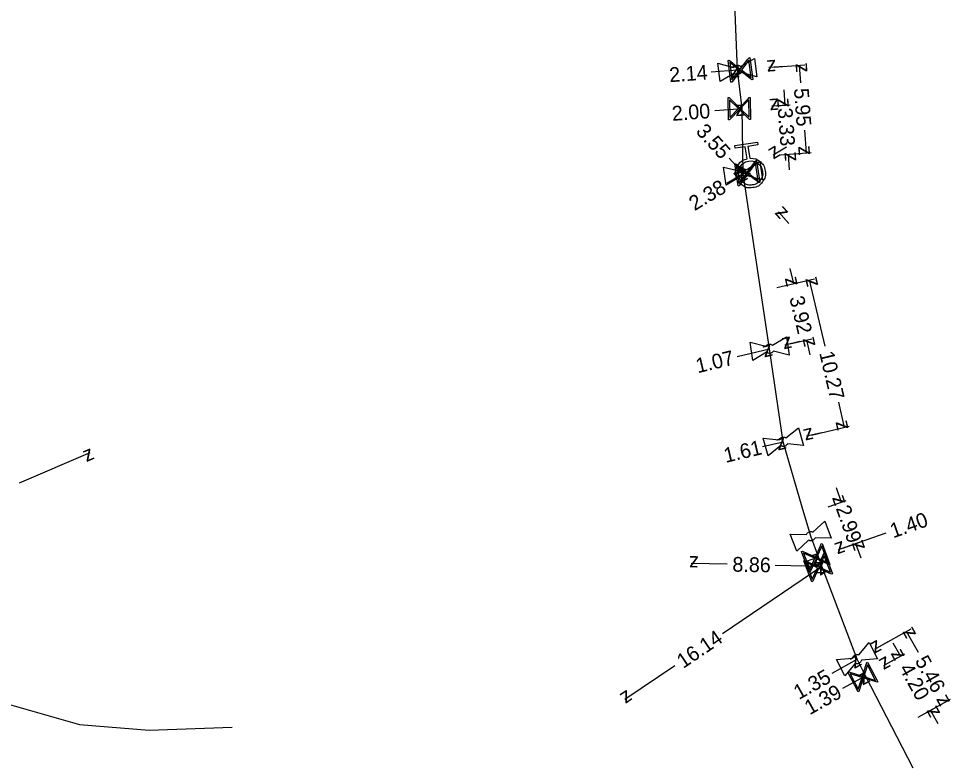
# Model space of a CAD drawing. Extents: x -638315 to -636370, y -1116147 to -1115110.
# Drawn here: x -637168.7 to -637105.5, y -1115879.5 to -1115828.9 of the extents above; entities that cross this region are included whole.
import ezdxf

# ---------------------------------------------------------------- set-up
doc = ezdxf.new("R2010")
doc.units = 0
for name, color, linetype in [('Default', 7, 'Continuous'), ('VP Hydrant', 7, 'Continuous'), ('VP Kótování', 7, 'Continuous'), ('VP Lomový bod', 7, 'Continuous'), ('VP Přípojka', 7, 'Continuous'), ('VP Řad', 7, 'Continuous'), ('VP Šoupě', 7, 'Continuous')]:
    doc.layers.add(name, color=color, linetype=linetype)

msp = doc.modelspace()

# ---------------------------------------------------------------- linework, layer by layer
at = {"layer": 'Default'}
for points in [[(-637120.251, -1115832.204), (-637120.222, -1115832.16), (-637120.178, -1115832.127), (-637120.111, -1115832.077), (-637120.03, -1115832.067), (-637119.948, -1115832.057), (-637119.868, -1115832.089), (-637119.819, -1115832.109), (-637119.78, -1115832.145)], [(-637119.729, -1115832.55), (-637119.758, -1115832.594), (-637119.8, -1115832.626), (-637119.87, -1115832.677), (-637119.951, -1115832.687), (-637120.032, -1115832.697), (-637120.11, -1115832.665), (-637120.161, -1115832.644), (-637120.2, -1115832.609)], [(-637119.158, -1115838.372), (-637118.798, -1115838.347), (-637118.505, -1115838.565), (-637118.173, -1115838.811), (-637118.111, -1115839.222), (-637118.049, -1115839.632), (-637118.295, -1115839.964), (-637118.541, -1115840.297), (-637118.952, -1115840.359), (-637119.359, -1115840.421), (-637119.693, -1115840.176), (-637120.026, -1115839.931), (-637120.088, -1115839.522), (-637120.15, -1115839.11), (-637119.907, -1115838.777), (-637119.691, -1115838.48), (-637119.34, -1115838.399)], [(-637119.224, -1115838.565), (-637119.558, -1115838.616), (-637119.757, -1115838.886), (-637119.956, -1115839.156), (-637119.905, -1115839.49), (-637119.855, -1115839.824), (-637119.585, -1115840.023), (-637119.314, -1115840.222), (-637118.98, -1115840.172), (-637118.648, -1115840.122), (-637118.448, -1115839.851), (-637118.248, -1115839.581), (-637118.299, -1115839.247), (-637118.349, -1115838.913), (-637118.619, -1115838.714), (-637118.89, -1115838.515), (-637119.224, -1115838.565)], [(-637119.875, -1115839.226), (-637119.847, -1115839.181), (-637119.804, -1115839.147), (-637119.738, -1115839.095), (-637119.657, -1115839.083), (-637119.576, -1115839.071), (-637119.495, -1115839.101), (-637119.445, -1115839.12), (-637119.405, -1115839.155)], [(-637119.344, -1115839.559), (-637119.372, -1115839.603), (-637119.414, -1115839.636), (-637119.482, -1115839.689), (-637119.563, -1115839.701), (-637119.644, -1115839.713), (-637119.723, -1115839.683), (-637119.774, -1115839.664), (-637119.814, -1115839.629)], [(-637118.074, -1115851.113), (-637118.046, -1115851.068), (-637118.003, -1115851.035), (-637117.937, -1115850.983), (-637117.856, -1115850.971), (-637117.775, -1115850.959), (-637117.694, -1115850.991), (-637117.644, -1115851.009), (-637117.604, -1115851.044)], [(-637117.545, -1115851.449), (-637117.573, -1115851.492), (-637117.615, -1115851.526), (-637117.684, -1115851.578), (-637117.765, -1115851.59), (-637117.845, -1115851.601), (-637117.924, -1115851.571), (-637117.975, -1115851.551), (-637118.015, -1115851.517)], [(-637117.164, -1115857.461), (-637117.143, -1115857.413), (-637117.104, -1115857.374), (-637117.046, -1115857.313), (-637116.967, -1115857.29), (-637116.888, -1115857.268), (-637116.804, -1115857.287), (-637116.752, -1115857.299), (-637116.708, -1115857.328)], [(-637116.594, -1115857.721), (-637116.616, -1115857.768), (-637116.653, -1115857.807), (-637116.714, -1115857.868), (-637116.793, -1115857.891), (-637116.871, -1115857.913), (-637116.953, -1115857.894), (-637117.006, -1115857.881), (-637117.05, -1115857.852)], [(-637115.313, -1115863.883), (-637115.295, -1115863.833), (-637115.26, -1115863.791), (-637115.206, -1115863.727), (-637115.13, -1115863.698), (-637115.053, -1115863.669), (-637114.967, -1115863.682), (-637114.915, -1115863.69), (-637114.869, -1115863.716)], [(-637114.725, -1115864.098), (-637114.743, -1115864.147), (-637114.777, -1115864.189), (-637114.833, -1115864.254), (-637114.91, -1115864.283), (-637114.986, -1115864.312), (-637115.069, -1115864.299), (-637115.123, -1115864.29), (-637115.17, -1115864.265)], [(-637112.184, -1115872.257), (-637112.172, -1115872.206), (-637112.142, -1115872.16), (-637112.095, -1115872.09), (-637112.023, -1115872.052), (-637111.95, -1115872.015), (-637111.863, -1115872.018), (-637111.81, -1115872.02), (-637111.761, -1115872.04)], [(-637111.574, -1115872.404), (-637111.587, -1115872.454), (-637111.616, -1115872.499), (-637111.664, -1115872.571), (-637111.737, -1115872.608), (-637111.81, -1115872.645), (-637111.894, -1115872.642), (-637111.948, -1115872.64), (-637111.997, -1115872.62)]]:
    msp.add_open_spline(points, degree=3, dxfattribs=at)
at = {"layer": 'VP Hydrant'}
msp.add_lwpolyline([(-637119.34, -1115838.399), (-637119.462, -1115837.588), (-637120.144, -1115837.691), (-637120.172, -1115837.51), (-637118.627, -1115837.276), (-637118.599, -1115837.457), (-637119.281, -1115837.56), (-637119.158, -1115838.372)], dxfattribs=at)
at = {"layer": 'VP Kótování'}
for points in [[(-637116.808, -1115832.144), (-637117.855, -1115832.221)], [(-637117.506, -1115832.195), (-637115.425, -1115832.043)], [(-637115.686, -1115833.258), (-637115.774, -1115832.069)], [(-637121.766, -1115832.507), (-637119.99, -1115832.377)], [(-637116.849, -1115833.728), (-637116.772, -1115834.775)], [(-637121.531, -1115835.123), (-637119.661, -1115834.986)], [(-637116.616, -1115834.763), (-637117.663, -1115834.84)], [(-637117.314, -1115834.814), (-637116.423, -1115834.749)], [(-637115.452, -1115836.46), (-637115.339, -1115838.008)], [(-637116.671, -1115837.617), (-637117.57, -1115838.16)], [(-637120.56, -1115838.355), (-637119.61, -1115839.392)], [(-637117.071, -1115838.134), (-637114.99, -1115837.982)], [(-637117.071, -1115838.134), (-637116.18, -1115838.069)], [(-637116.453, -1115839.142), (-637116.529, -1115838.095)], [(-637120.703, -1115840.052), (-637119.61, -1115839.392)], [(-637116.5, -1115842.784), (-637117.21, -1115842.01)], [(-637116.427, -1115845.848), (-637116.187, -1115846.87)], [(-637117.329, -1115847.14), (-637114.76, -1115846.534)], [(-637114.041, -1115851.11), (-637115.1, -1115846.614)], [(-637117.329, -1115847.14), (-637115.846, -1115846.79)], [(-637115.749, -1115850.794), (-637116.771, -1115851.035)], [(-637116.43, -1115850.955), (-637114.947, -1115850.605)], [(-637115.047, -1115851.707), (-637115.288, -1115850.685)], [(-637120.019, -1115851.801), (-637117.81, -1115851.28)], [(-637113.144, -1115854.914), (-637112.743, -1115856.615)], [(-637114.972, -1115857.141), (-637112.403, -1115856.535)], [(-637114.291, -1115856.98), (-637115.313, -1115857.221)], [(-637118.292, -1115857.922), (-637116.88, -1115857.59)], [(-637168.693, -1115860.38), (-637163.89, -1115858.32)], [(-637113.294, -1115860.692), (-637112.945, -1115861.682)], [(-637113.83, -1115861.994), (-637112.615, -1115861.566)], [(-637109.926, -1115863.786), (-637113.168, -1115864.928)], [(-637112.838, -1115864.812), (-637111.623, -1115864.384)], [(-637111.604, -1115865.491), (-637111.953, -1115864.5)], [(-637115.481, -1115865.743), (-637114.491, -1115865.394)], [(-637120.679, -1115865.888), (-637123.12, -1115865.84)], [(-637121.004, -1115870.587), (-637114.258, -1115866.015)], [(-637117.439, -1115865.952), (-637114.258, -1115866.015)], [(-637110.397, -1115871.502), (-637108.211, -1115870.281)], [(-637107.714, -1115871.887), (-637108.516, -1115870.451)], [(-637109.786, -1115871.161), (-637110.703, -1115871.673)], [(-637109.45, -1115871.212), (-637108.938, -1115872.128)], [(-637109.783, -1115872.6), (-637108.633, -1115871.958)], [(-637113.57, -1115873.273), (-637111.88, -1115872.33)], [(-637109.172, -1115872.259), (-637110.089, -1115872.771)], [(-637124.239, -1115872.779), (-637127.62, -1115875.07)], [(-637112.835, -1115874.306), (-637111.304, -1115873.45)], [(-637107.734, -1115876.269), (-637105.548, -1115875.048)], [(-637107.734, -1115876.269), (-637106.584, -1115875.627)], [(-637106.377, -1115876.714), (-637106.889, -1115875.797)]]:
    msp.add_lwpolyline(points, dxfattribs=at)
at = {"layer": 'VP Lomový bod'}
for points in [[(-637120.2, -1115832.609), (-637121.152, -1115833.153), (-637121.309, -1115831.913), (-637120.251, -1115832.204)], [(-637119.78, -1115832.145), (-637118.828, -1115831.6)], [(-637118.828, -1115831.6), (-637118.672, -1115832.84), (-637119.729, -1115832.55)], [(-637119.814, -1115839.629), (-637120.752, -1115840.197), (-637120.939, -1115838.961), (-637119.875, -1115839.226)], [(-637119.405, -1115839.155), (-637118.468, -1115838.587)], [(-637118.468, -1115838.587), (-637118.28, -1115839.823), (-637119.344, -1115839.559)], [(-637117.604, -1115851.044), (-637116.665, -1115850.48)], [(-637116.665, -1115850.48), (-637116.482, -1115851.716), (-637117.545, -1115851.449)], [(-637118.015, -1115851.517), (-637118.956, -1115852.081), (-637119.138, -1115850.844), (-637118.074, -1115851.113)], [(-637116.708, -1115857.328), (-637115.854, -1115856.641)], [(-637115.854, -1115856.641), (-637115.505, -1115857.842), (-637116.594, -1115857.721)], [(-637117.05, -1115857.852), (-637117.906, -1115858.54), (-637118.255, -1115857.339), (-637117.164, -1115857.461)], [(-637114.869, -1115863.716), (-637114.07, -1115862.965)], [(-637114.07, -1115862.965), (-637113.63, -1115864.135), (-637114.725, -1115864.098)], [(-637115.17, -1115864.265), (-637115.969, -1115865.016), (-637116.41, -1115863.846), (-637115.313, -1115863.883)], [(-637111.761, -1115872.04), (-637111.054, -1115871.203)], [(-637111.054, -1115871.203), (-637110.482, -1115872.314), (-637111.574, -1115872.404)], [(-637111.997, -1115872.62), (-637112.706, -1115873.457), (-637113.277, -1115872.346), (-637112.184, -1115872.257)]]:
    msp.add_lwpolyline(points, dxfattribs=at)
at = {"layer": 'VP Přípojka'}
for points in [[(-637119.79, -1115832.38), (-637119.99, -1115832.377)], [(-637119.661, -1115834.986), (-637119.86, -1115835)], [(-637119.61, -1115839.392), (-637119.1, -1115839.37)], [(-637114.491, -1115865.394), (-637114.679, -1115865.464)], [(-637114.258, -1115866.015), (-637114.445, -1115866.085)], [(-637180.72, -1115868.647), (-637180.66, -1115868.69), (-637179.56, -1115869.48), (-637175.49, -1115872.98), (-637170.49, -1115875.08), (-637164.61, -1115876.76), (-637159.9, -1115877.14), (-637154.27, -1115876.95)], [(-637111.304, -1115873.45), (-637111.482, -1115873.541)]]:
    msp.add_lwpolyline(points, dxfattribs=at)
at = {"layer": 'VP Řad'}
msp.add_lwpolyline([(-637108.074, -1115879.731), (-637111.304, -1115873.45), (-637111.88, -1115872.33), (-637114.258, -1115866.015), (-637114.492, -1115865.394), (-637115.02, -1115863.99), (-637115.594, -1115862.016), (-637116.88, -1115857.59), (-637117.81, -1115851.28), (-637119.61, -1115839.392), (-637119.661, -1115834.986), (-637119.99, -1115832.377), (-637120.35, -1115823.44)], dxfattribs=at)
at = {"layer": 'VP Šoupě'}
for points in [[(-637119.139, -1115831.542), (-637118.952, -1115833.03), (-637119.017, -1115833.039), (-637119.116, -1115832.957), (-637119.78, -1115832.442), (-637120.375, -1115833.21), (-637120.44, -1115833.218), (-637120.628, -1115831.73), (-637120.562, -1115831.722), (-637119.796, -1115832.319), (-637119.282, -1115831.655), (-637119.205, -1115831.55), (-637119.139, -1115831.542)], [(-637120.366, -1115833.055), (-637119.85, -1115832.388), (-637120.515, -1115831.874), (-637120.366, -1115833.055)], [(-637119.213, -1115831.71), (-637119.726, -1115832.373), (-637119.065, -1115832.885), (-637119.213, -1115831.71)], [(-637119.118, -1115834.242), (-637119.101, -1115835.742), (-637119.167, -1115835.742), (-637119.256, -1115835.65), (-637119.858, -1115835.063), (-637120.535, -1115835.758), (-637120.601, -1115835.759), (-637120.618, -1115834.259), (-637120.552, -1115834.258), (-637119.859, -1115834.939), (-637119.273, -1115834.337), (-637119.184, -1115834.243), (-637119.118, -1115834.242)], [(-637120.509, -1115835.606), (-637119.921, -1115835.002), (-637120.523, -1115834.415), (-637120.509, -1115835.606)], [(-637119.21, -1115834.4), (-637119.796, -1115835), (-637119.197, -1115835.585), (-637119.21, -1115834.4)], [(-637118.686, -1115838.529), (-637118.462, -1115840.012), (-637118.527, -1115840.022), (-637118.628, -1115839.943), (-637119.305, -1115839.445), (-637119.88, -1115840.227), (-637119.945, -1115840.237), (-637120.17, -1115838.754), (-637120.104, -1115838.744), (-637119.323, -1115839.322), (-637118.826, -1115838.645), (-637118.752, -1115838.539), (-637118.686, -1115838.529)], [(-637119.875, -1115840.072), (-637119.376, -1115839.393), (-637120.053, -1115838.895), (-637119.875, -1115840.072)], [(-637118.756, -1115838.699), (-637119.253, -1115839.374), (-637118.578, -1115839.87), (-637118.756, -1115838.699)], [(-637114.241, -1115864.498), (-637113.712, -1115865.901), (-637113.774, -1115865.925), (-637113.889, -1115865.868), (-637114.655, -1115865.522), (-637115.054, -1115866.407), (-637115.116, -1115866.43), (-637115.645, -1115865.026), (-637115.583, -1115865.003), (-637114.699, -1115865.406), (-637114.353, -1115864.64), (-637114.302, -1115864.521), (-637114.241, -1115864.498)], [(-637114.273, -1115864.678), (-637114.618, -1115865.442), (-637113.856, -1115865.786), (-637114.273, -1115864.678)], [(-637115.082, -1115866.254), (-637114.735, -1115865.486), (-637115.502, -1115865.14), (-637115.082, -1115866.254)], [(-637114.073, -1115865.144), (-637113.544, -1115866.547), (-637113.606, -1115866.571), (-637113.721, -1115866.514), (-637114.487, -1115866.168), (-637114.886, -1115867.053), (-637114.948, -1115867.076), (-637115.477, -1115865.672), (-637115.415, -1115865.649), (-637114.531, -1115866.052), (-637114.185, -1115865.286), (-637114.134, -1115865.167), (-637114.073, -1115865.144)], [(-637114.105, -1115865.324), (-637114.45, -1115866.088), (-637113.688, -1115866.432), (-637114.105, -1115865.324)], [(-637114.914, -1115866.9), (-637114.567, -1115866.132), (-637115.334, -1115865.786), (-637114.914, -1115866.9)], [(-637111.157, -1115872.531), (-637110.471, -1115873.865), (-637110.53, -1115873.895), (-637110.651, -1115873.852), (-637111.451, -1115873.596), (-637111.746, -1115874.521), (-637111.805, -1115874.551), (-637112.491, -1115873.217), (-637112.432, -1115873.187), (-637111.508, -1115873.486), (-637111.252, -1115872.685), (-637111.216, -1115872.561), (-637111.157, -1115872.531)], [(-637111.168, -1115872.714), (-637111.424, -1115873.513), (-637110.627, -1115873.767), (-637111.168, -1115872.714)], [(-637111.791, -1115874.373), (-637111.535, -1115873.569), (-637112.336, -1115873.314), (-637111.791, -1115874.373)]]:
    msp.add_lwpolyline(points, dxfattribs=at)

# ---------------------------------------------------------------- texts
at = {"layer": 'VP Kótování'}
for s, rotation, p in [('2.14', 4.17904, (-637124.58, -1115833.214)), ('z', 4.17904, (-637120.452, -1115832.912)), ('z', 184.17908, (-637117.393, -1115831.686)), ('z', 94.1891, (-637115.238, -1115832.531)), ('5.95', 274.18912, (-637116.16, -1115833.644)), ('2.00', 4.17933, (-637124.4, -1115835.834)), ('z', 4.17933, (-637120.123, -1115835.521)), ('z', 184.17936, (-637117.201, -1115834.305)), ('z', 274.18616, (-637117.308, -1115834.313)), ('3.33', 274.18615, (-637117.258, -1115834.983)), ('3.55', 312.51244, (-637122.862, -1115836.585)), ('z', 211.12866, (-637117.4, -1115837.474)), ('z', 274.18914, (-637115.874, -1115837.545)), ('z', 94.18618, (-637115.994, -1115838.557)), ('z', 312.51246, (-637120.316, -1115839.361)), ('z', 31.12868, (-637119.78, -1115840.078)), ('2.38', 31.12868, (-637122.891, -1115841.958)), ('z', 132.51242, (-637116.504, -1115842.041)), ('z', 283.25975, (-637116.788, -1115846.498)), ('z', 103.26126, (-637114.499, -1115846.986)), ('3.92', 283.25979, (-637116.475, -1115847.827)), ('z', 193.26819, (-637116.399, -1115850.434)), ('z', 103.25977, (-637114.686, -1115851.057)), ('z', 13.26816, (-637118.182, -1115851.881)), ('1.07', 13.26816, (-637122.686, -1115852.944)), ('10.27', 283.26128, (-637114.447, -1115851.566)), ('z', 283.2613, (-637113.345, -1115856.243)), ('z', 193.25072, (-637114.941, -1115856.62)), ('z', 13.25074, (-637117.252, -1115858.191)), ('z', 23.2198, (-637164.152, -1115858.977)), ('1.61', 13.25074, (-637120.789, -1115859.024)), ('z', 289.39321, (-637113.583, -1115861.377)), ('2.99', 289.39325, (-637113.329, -1115862.098)), ('1.40', 19.40379, (-637109.43, -1115864.141)), ('z', 199.40377, (-637112.863, -1115864.29)), ('z', 109.39323, (-637111.315, -1115864.806)), ('z', 178.86871, (-637122.61, -1115865.35)), ('8.86', 358.86873, (-637120.339, -1115866.395)), ('z', 19.40379, (-637114.796, -1115866.032)), ('z', 34.12422, (-637114.391, -1115866.709)), ('z', 358.86869, (-637114.768, -1115866.505)), ('16.14', 34.12422, (-637123.669, -1115872.997)), ('z', 119.18914, (-637107.836, -1115870.644)), ('z', 209.17018, (-637110.51, -1115870.993)), ('z', 299.18173, (-637109.619, -1115871.936)), ('z', 29.1702, (-637112.073, -1115873.01)), ('z', 209.19854, (-637109.896, -1115872.091)), ('5.46', 299.18911, (-637107.98, -1115872.436)), ('1.35', 29.1702, (-637115.823, -1115875.104)), ('z', 29.19856, (-637111.497, -1115874.13)), ('4.20', 299.18172, (-637109.047, -1115872.958)), ('z', 214.12426, (-637127.487, -1115874.376)), ('1.39', 29.19856, (-637115.086, -1115876.137)), ('z', 299.18912, (-637106.533, -1115875.026)), ('z', 119.18175, (-637106.209, -1115875.99))]:
    msp.add_text(s, height=1, rotation=rotation, dxfattribs=at).set_placement(p)

doc.saveas('drawing.dxf')
